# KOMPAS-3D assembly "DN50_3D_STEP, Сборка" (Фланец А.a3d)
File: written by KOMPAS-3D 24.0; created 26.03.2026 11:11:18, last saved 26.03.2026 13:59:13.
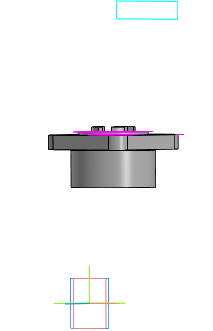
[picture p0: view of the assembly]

Document properties: Автор: R2D2; Полное имя файла: E:\Работа\Зайцев\GVWR2434M-2W-F-ОСТ Задвижка клиновая с выдвижным штоком DN.ru Ду50-300 Ру25\исходные материалы\DN50\Фланец А.a3d

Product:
- Body: Тело 2  | qty 1
    Масса: 2.709631
- Part/product: DN50_3D_STEP  | designation Сборка
    Масса: 2.725126

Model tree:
1. Перпендикулярная плоскость:2
     Координата Z = -90
2. Операция без истории:2
3. Эскиз:1  (with: Грань.Операция без истории:2, Ребро.Операция без истории:2)
4. Элемент выдавливания:1  (with: Грань.Операция без истории:2)
     Расстояние 2 = 14.5
5. Массив по концентрической сетке:1  (with: Элемент выдавливания:1, Грань.Операция без истории:2)  (4 pattern instances)
     Шаг 2 = 360
6. Скругление:1
     Радиус = 13.5
7. Эскиз:2  (with: Грань.Операция без истории:2, Ребро.Операция без истории:2)
8. Элемент выдавливания:2
     Расстояние 2 = 20
9. Эскиз:3  (with: Грань.Операция без истории:2, Ребро.Операция без истории:2)
10. Элемент выдавливания:3  (with: Грань.Операция без истории:2)
     Расстояние 2 = 3
11. Эскиз:4  (with: Грань.Операция без истории:2, Ребро.Операция без истории:2)
12. Элемент выдавливания:4
     Расстояние 1 = 3
13. Эскиз:5  (with: Грань.Операция без истории:2, Ребро.Операция без истории:2)
14. Элемент выдавливания:5
     Расстояние 1 = 1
